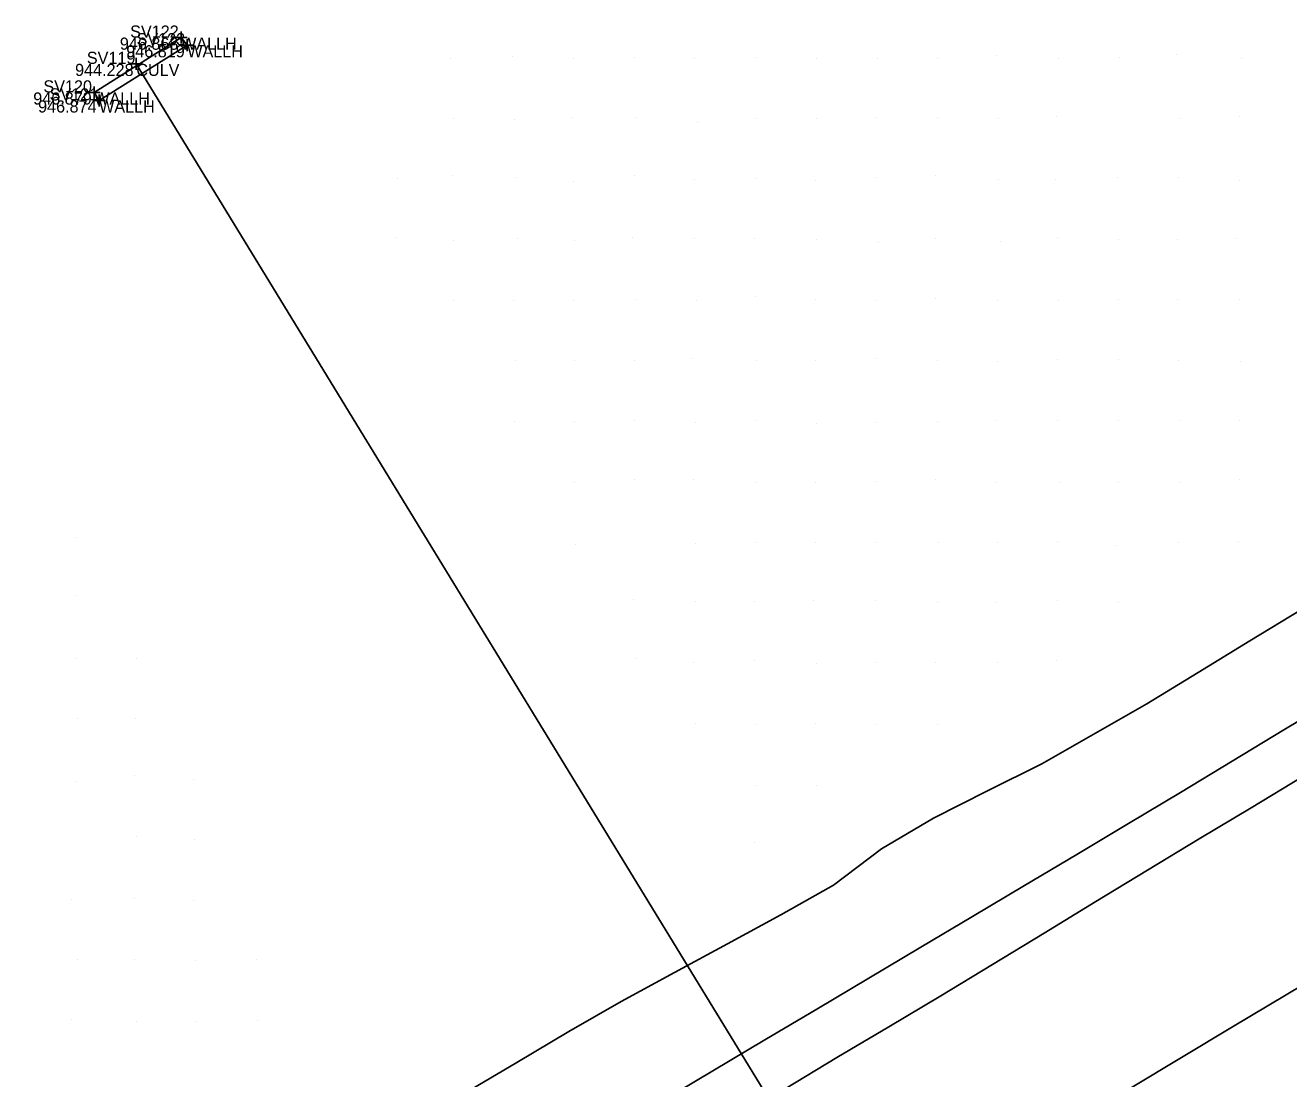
# Model space of a CAD drawing. Extents: x 2262025 to 2264532, y 740981 to 742724.
# Drawn here: x 2263294.3 to 2263398.7, y 741888.7 to 741975.7 of the extents above; entities that cross this region are included whole.
import ezdxf

# ---------------------------------------------------------------- set-up
doc = ezdxf.new("R2010")
doc.units = 0
for name, color, linetype in [('GE_X_Alignment_100_Curve_Data', 7, 'Continuous'), ('Ground Shots', 7, 'Continuous'), ('HY_X_Spring_Cells', 7, 'Continuous'), ('RW_X_CL', 7, 'Continuous'), ('RW_X_CL_1000_Distances', 7, 'Continuous'), ('RW_X_CL_100_Cardinal_Points', 7, 'Continuous'), ('RW_X_CL_500_Cardinal_Points', 7, 'Continuous'), ('RW_X_CL_500_Stations', 7, 'Continuous'), ('SV_X_Control_Cells_Found', 7, 'Continuous'), ('SV_X_Text_Comment', 7, 'Continuous')]:
    doc.layers.add(name, color=color, linetype=linetype)

msp = doc.modelspace()

# ---------------------------------------------------------------- linework, layer by layer
at = {"layer": 'GE_X_Alignment_100_Curve_Data'}
msp.add_lwpolyline([(2263346.83, 741886.79), (2263351.13, 741889.34), (2263355.43, 741891.89), (2263359.72, 741894.44), (2263364.02, 741897), (2263368.32, 741899.55), (2263372.61, 741902.1), (2263376.91, 741904.65), (2263381.21, 741907.21), (2263385.49, 741909.78), (2263389.78, 741912.35), (2263394.06, 741914.93), (2263398.34, 741917.51), (2263402.62, 741920.09)], dxfattribs=at)
at = {"layer": 'Ground Shots'}
for p, q in [((2263334.61, 741973.19), (2263334.61, 741973.19)), ((2263344.63, 741973.1), (2263344.63, 741973.1)), ((2263374.62, 741973.21), (2263374.62, 741973.21)), ((2263384.75, 741973.1), (2263384.75, 741973.1)), ((2263389.44, 741973.31), (2263389.44, 741973.31)), ((2263329.43, 741973), (2263329.43, 741973)), ((2263339.6, 741973.02), (2263339.6, 741973.02)), ((2263349.61, 741973.02), (2263349.61, 741973.02)), ((2263354.63, 741973.07), (2263354.63, 741973.07)), ((2263359.7, 741972.99), (2263359.7, 741972.99)), ((2263364.75, 741973), (2263364.75, 741973)), ((2263369.71, 741972.98), (2263369.71, 741972.98)), ((2263379.72, 741973.01), (2263379.72, 741973.01)), ((2263394.84, 741973), (2263394.84, 741973)), ((2263329.72, 741968), (2263329.72, 741968)), ((2263334.7, 741967.94), (2263334.7, 741967.94)), ((2263339.45, 741968.08), (2263339.45, 741968.08)), ((2263344.73, 741968.08), (2263344.73, 741968.08)), ((2263354.65, 741968.05), (2263354.65, 741968.05)), ((2263359.68, 741968.01), (2263359.68, 741968.01)), ((2263364.7, 741968.12), (2263364.7, 741968.12)), ((2263369.72, 741968.09), (2263369.72, 741968.09)), ((2263374.76, 741968.06), (2263374.76, 741968.06)), ((2263379.57, 741968.18), (2263379.57, 741968.18)), ((2263389.69, 741968.02), (2263389.69, 741968.02)), ((2263394.68, 741968.17), (2263394.68, 741968.17)), ((2263349.86, 741967.69), (2263349.86, 741967.69)), ((2263325.09, 741963.04), (2263325.09, 741963.04)), ((2263329.59, 741963.32), (2263329.59, 741963.32)), ((2263334.82, 741963.15), (2263334.82, 741963.15)), ((2263339.6, 741962.81), (2263339.6, 741962.81)), ((2263344.67, 741963.32), (2263344.67, 741963.32)), ((2263349.63, 741962.97), (2263349.63, 741962.97)), ((2263354.69, 741963.06), (2263354.69, 741963.06)), ((2263359.66, 741962.95), (2263359.66, 741962.95)), ((2263364.54, 741963.12), (2263364.54, 741963.12)), ((2263369.54, 741963.31), (2263369.54, 741963.31)), ((2263374.78, 741962.99), (2263374.78, 741962.99)), ((2263379.42, 741963.01), (2263379.42, 741963.01)), ((2263384.58, 741963.13), (2263384.58, 741963.13)), ((2263389.59, 741963.19), (2263389.59, 741963.19)), ((2263394.69, 741962.95), (2263394.69, 741962.95)), ((2263325.02, 741958.23), (2263325.02, 741958.23)), ((2263329.74, 741957.99), (2263329.74, 741957.99)), ((2263334.96, 741958.16), (2263334.96, 741958.16)), ((2263339.67, 741957.99), (2263339.67, 741957.99)), ((2263344.53, 741958.17), (2263344.53, 741958.17)), ((2263349.61, 741958.16), (2263349.61, 741958.16)), ((2263354.61, 741958.09), (2263354.61, 741958.09)), ((2263359.73, 741958), (2263359.73, 741958)), ((2263364.86, 741957.78), (2263364.86, 741957.78)), ((2263369.57, 741958.12), (2263369.57, 741958.12)), ((2263374.9, 741957.85), (2263374.9, 741957.85)), ((2263379.65, 741958.17), (2263379.65, 741958.17)), ((2263384.69, 741958.06), (2263384.69, 741958.06)), ((2263389.52, 741958.06), (2263389.52, 741958.06)), ((2263394.32, 741958.09), (2263394.32, 741958.09)), ((2263354.63, 741953.31), (2263354.63, 741953.31)), ((2263329.7, 741953), (2263329.7, 741953)), ((2263334.67, 741952.97), (2263334.67, 741952.97)), ((2263339.65, 741953.01), (2263339.65, 741953.01)), ((2263344.74, 741953.09), (2263344.74, 741953.09)), ((2263349.77, 741953.01), (2263349.77, 741953.01)), ((2263359.65, 741953.04), (2263359.65, 741953.04)), ((2263364.68, 741953), (2263364.68, 741953)), ((2263369.57, 741953.13), (2263369.57, 741953.13)), ((2263374.68, 741953.01), (2263374.68, 741953.01)), ((2263379.68, 741953.01), (2263379.68, 741953.01)), ((2263384.7, 741953.07), (2263384.7, 741953.07)), ((2263389.51, 741953.09), (2263389.51, 741953.09)), ((2263394.65, 741953.05), (2263394.65, 741953.05)), ((2263334.82, 741948.04), (2263334.82, 741948.04)), ((2263339.74, 741948.03), (2263339.74, 741948.03)), ((2263349.49, 741948.18), (2263349.49, 741948.18)), ((2263364.6, 741948.18), (2263364.6, 741948.18)), ((2263369.72, 741948.04), (2263369.72, 741948.04)), ((2263379.61, 741948.11), (2263379.61, 741948.11)), ((2263384.63, 741948.13), (2263384.63, 741948.13)), ((2263389.63, 741948.06), (2263389.63, 741948.06)), ((2263344.68, 741948.02), (2263344.68, 741948.02)), ((2263354.71, 741948), (2263354.71, 741948)), ((2263359.66, 741948.02), (2263359.66, 741948.02)), ((2263374.68, 741947.95), (2263374.68, 741947.95)), ((2263394.76, 741947.99), (2263394.76, 741947.99)), ((2263334.72, 741942.98), (2263334.72, 741942.98)), ((2263339.71, 741942.99), (2263339.71, 741942.99)), ((2263344.68, 741943.06), (2263344.68, 741943.06)), ((2263349.67, 741942.94), (2263349.67, 741942.94)), ((2263354.72, 741943.1), (2263354.72, 741943.1)), ((2263359.71, 741942.87), (2263359.71, 741942.87)), ((2263364.67, 741942.93), (2263364.67, 741942.93)), ((2263369.71, 741943.01), (2263369.71, 741943.01)), ((2263374.62, 741943.04), (2263374.62, 741943.04)), ((2263379.63, 741943.09), (2263379.63, 741943.09)), ((2263384.66, 741943.05), (2263384.66, 741943.05)), ((2263389.68, 741943.09), (2263389.68, 741943.09)), ((2263394.65, 741943.04), (2263394.65, 741943.04)), ((2263339.73, 741937.97), (2263339.73, 741937.97)), ((2263344.67, 741938.2), (2263344.67, 741938.2)), ((2263349.57, 741938.24), (2263349.57, 741938.24)), ((2263354.74, 741937.97), (2263354.74, 741937.97)), ((2263359.64, 741937.92), (2263359.64, 741937.92)), ((2263364.6, 741938.08), (2263364.6, 741938.08)), ((2263369.5, 741938.18), (2263369.5, 741938.18)), ((2263374.59, 741937.95), (2263374.59, 741937.95)), ((2263379.75, 741937.93), (2263379.75, 741937.93)), ((2263384.68, 741937.93), (2263384.68, 741937.93)), ((2263389.69, 741937.97), (2263389.69, 741937.97)), ((2263394.63, 741938.2), (2263394.63, 741938.2)), ((2263298.51, 741933.41), (2263298.51, 741933.41)), ((2263339.78, 741932.86), (2263339.78, 741932.86)), ((2263349.71, 741932.95), (2263349.71, 741932.95)), ((2263354.7, 741932.98), (2263354.7, 741932.98)), ((2263359.62, 741933), (2263359.62, 741933)), ((2263364.66, 741932.97), (2263364.66, 741932.97)), ((2263369.77, 741932.98), (2263369.77, 741932.98)), ((2263374.67, 741932.97), (2263374.67, 741932.97)), ((2263379.63, 741933.08), (2263379.63, 741933.08)), ((2263384.43, 741932.77), (2263384.43, 741932.77)), ((2263389.65, 741933.02), (2263389.65, 741933.02)), ((2263394.56, 741933.05), (2263394.56, 741933.05)), ((2263298.43, 741928.58), (2263298.43, 741928.58)), ((2263344.57, 741928.28), (2263344.57, 741928.28)), ((2263359.49, 741928.21), (2263359.49, 741928.21)), ((2263364.62, 741928.2), (2263364.62, 741928.2)), ((2263379.62, 741928.2), (2263379.62, 741928.2)), ((2263349.72, 741928.09), (2263349.72, 741928.09)), ((2263354.61, 741928.14), (2263354.61, 741928.14)), ((2263369.67, 741928.05), (2263369.67, 741928.05)), ((2263374.61, 741928.06), (2263374.61, 741928.06)), ((2263384.67, 741928.05), (2263384.67, 741928.05)), ((2263298.47, 741923.42), (2263298.47, 741923.42)), ((2263303.52, 741923.38), (2263303.52, 741923.38)), ((2263344.83, 741923.38), (2263344.83, 741923.38)), ((2263349.52, 741923.06), (2263349.52, 741923.06)), ((2263354.61, 741923.27), (2263354.61, 741923.27)), ((2263359.68, 741923.04), (2263359.68, 741923.04)), ((2263364.61, 741923.09), (2263364.61, 741923.09)), ((2263369.52, 741923.06), (2263369.52, 741923.06)), ((2263374.64, 741923.07), (2263374.64, 741923.07)), ((2263379.51, 741923.26), (2263379.51, 741923.26)), ((2263298.58, 741918.44), (2263298.58, 741918.44)), ((2263303.44, 741918.49), (2263303.44, 741918.49)), ((2263349.69, 741918.01), (2263349.69, 741918.01)), ((2263354.74, 741917.93), (2263354.74, 741917.93)), ((2263359.65, 741918.04), (2263359.65, 741918.04)), ((2263364.7, 741917.94), (2263364.7, 741917.94)), ((2263369.67, 741918), (2263369.67, 741918)), ((2263303.35, 741913.71), (2263303.35, 741913.71)), ((2263298.51, 741913.24), (2263298.51, 741913.24)), ((2263308.17, 741913.39), (2263308.17, 741913.39)), ((2263354.69, 741912.96), (2263354.69, 741912.96)), ((2263359.72, 741912.94), (2263359.72, 741912.94)), ((2263303.53, 741908.67), (2263303.53, 741908.67)), ((2263308.26, 741908.49), (2263308.26, 741908.49)), ((2263354.62, 741908.25), (2263354.62, 741908.25)), ((2263298.14, 741903.51), (2263298.14, 741903.51)), ((2263303.36, 741903.59), (2263303.36, 741903.59)), ((2263308.19, 741903.42), (2263308.19, 741903.42)), ((2263298.6, 741898.51), (2263298.6, 741898.51)), ((2263303.34, 741898.56), (2263303.34, 741898.56)), ((2263308.37, 741898.45), (2263308.37, 741898.45)), ((2263313.38, 741898.54), (2263313.38, 741898.54)), ((2263298.15, 741893.6), (2263298.15, 741893.6)), ((2263303.51, 741893.42), (2263303.51, 741893.42)), ((2263308.45, 741893.45), (2263308.45, 741893.45)), ((2263313.46, 741893.46), (2263313.46, 741893.46))]:
    msp.add_line(p, q, dxfattribs=at)
at = {"layer": 'RW_X_CL_1000_Distances'}
for points in [[(2263399.91, 741913.65), (2263395.62, 741911.08), (2263391.34, 741908.5), (2263387.06, 741905.92), (2263382.79, 741903.32), (2263378.53, 741900.71), (2263374.25, 741898.12), (2263369.97, 741895.54), (2263365.68, 741892.98), (2263361.39, 741890.43), (2263357.11, 741887.85)], [(2263223.49, 741788.99), (2263232, 741794.24), (2263240.53, 741799.45), (2263249.06, 741804.67), (2263257.6, 741809.88), (2263266.13, 741815.09), (2263274.68, 741820.27), (2263283.24, 741825.45), (2263291.79, 741830.63), (2263300.33, 741835.84), (2263308.83, 741841.1), (2263317.32, 741846.36), (2263325.83, 741851.62), (2263334.38, 741856.8), (2263342.93, 741861.98), (2263351.48, 741867.16), (2263360.01, 741872.37), (2263368.55, 741877.57), (2263377.08, 741882.78), (2263385.65, 741887.92), (2263394.24, 741893.05), (2263402.82, 741898.18)]]:
    msp.add_lwpolyline(points, dxfattribs=at)
at = {"layer": 'RW_X_CL_100_Cardinal_Points'}
for p, q in [((2263307.18, 741975.22), (2263307.18, 741974.22)), ((2263306.68, 741974.72), (2263307.68, 741974.72)), ((2263307.18, 741974.72), (2263307.18, 741974.72)), ((2263307.69, 741974.59), (2263307.69, 741973.59)), ((2263307.19, 741974.09), (2263308.19, 741974.09)), ((2263307.69, 741974.09), (2263307.69, 741974.09)), ((2263302.98, 741972.55), (2263303.98, 741972.55)), ((2263302.98, 741972.55), (2263303.98, 741972.55)), ((2263303.48, 741973.05), (2263303.48, 741972.05)), ((2263303.48, 741973.05), (2263303.48, 741972.05)), ((2263303.48, 741972.55), (2263303.48, 741972.55)), ((2263303.48, 741972.55), (2263303.48, 741972.55)), ((2263299.5, 741970.19), (2263300.5, 741970.19)), ((2263300, 741970.69), (2263300, 741969.69)), ((2263300, 741970.19), (2263300, 741970.19)), ((2263300.4, 741970.03), (2263300.4, 741969.03)), ((2263299.9, 741969.53), (2263300.9, 741969.53)), ((2263300.4, 741969.53), (2263300.4, 741969.53))]:
    msp.add_line(p, q, dxfattribs=at)
at = {"layer": 'RW_X_CL_500_Cardinal_Points'}
msp.add_lwpolyline([(2263300.4, 741969.53), (2263300, 741970.19), (2263307.18, 741974.72), (2263307.69, 741974.09)], close=True, dxfattribs=at)
at = {"layer": 'RW_X_CL_500_Stations'}
msp.add_line((2263303.48, 741972.55), (2263398.17, 741817.73), dxfattribs=at)
at = {"layer": 'SV_X_Control_Cells_Found'}
msp.add_lwpolyline([(2263399.8, 741927.47), (2263395.53, 741924.87), (2263391.26, 741922.27), (2263387, 741919.66), (2263378.32, 741914.71), (2263373.85, 741912.47), (2263369.38, 741910.23), (2263365.08, 741907.69), (2263361.11, 741904.67), (2263356.76, 741902.22), (2263352.36, 741899.84), (2263347.96, 741897.46), (2263343.57, 741895.08), (2263339.23, 741892.59), (2263334.93, 741890.04), (2263330.64, 741887.5)], dxfattribs=at)

# ---------------------------------------------------------------- texts
at = {"layer": 'HY_X_Spring_Cells'}
for s, p in [('946.868', (2263302.12, 741973.72)), ('946.819', (2263302.65, 741973.09)), ('944.228', (2263298.42, 741971.55)), ('944.228', (2263298.42, 741971.55)), ('946.879', (2263294.96, 741969.19)), ('946.874', (2263295.36, 741968.53))]:
    msp.add_text(s, height=1, dxfattribs=at).set_placement(p)
at = {"layer": 'RW_X_CL'}
for s, p in [('WALLH', (2263307.18, 741973.72)), ('WALLH', (2263307.69, 741973.09)), ('CULV', (2263303.48, 741971.55)), ('CULV', (2263303.48, 741971.55)), ('WALLH', (2263300, 741969.19)), ('WALLH', (2263300.4, 741968.53))]:
    msp.add_text(s, height=1, dxfattribs=at).set_placement(p)
at = {"layer": 'SV_X_Text_Comment'}
for s, p in [('SV122', (2263302.97, 741974.72)), ('SV123', (2263303.5, 741974.09)), ('SV119', (2263299.39, 741972.55)), ('SV119', (2263299.39, 741972.55)), ('SV120', (2263295.8, 741970.19)), ('SV121', (2263296.31, 741969.53))]:
    msp.add_text(s, height=1, dxfattribs=at).set_placement(p)

doc.saveas('drawing.dxf')
